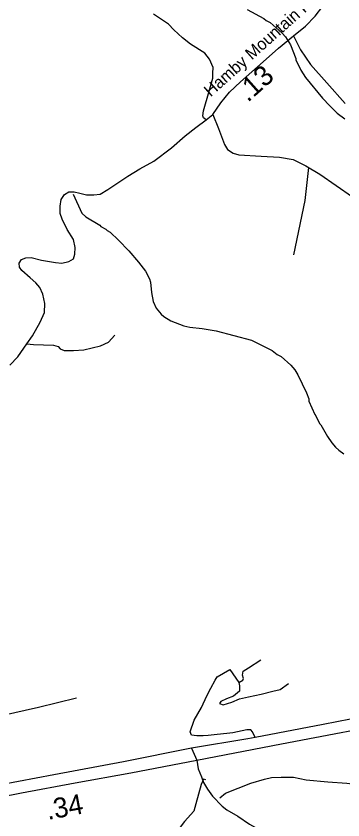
# Model space of a CAD drawing. Extents: x 1248224 to 1454986, y 825081 to 985870.
# Drawn here: x 1325316 to 1327358, y 878794 to 883811 of the extents above; entities that cross this region are included whole.
import ezdxf

# ---------------------------------------------------------------- set-up
doc = ezdxf.new("R2010")
doc.units = 0
for name, color, linetype in [('Exist Hydrographic Misc Water Feature', 7, 'Continuous'), ('Exist Road Non-System Type 51', 7, 'Continuous'), ('Exist Road Primary US Divided Attributed', 7, 'Continuous'), ('Exist Road Primary US Mileage Hundredths English Label', 7, 'Continuous'), ('Exist Road Secondary Mileage Hundredths English Label', 7, 'Continuous'), ('Exist Road Secondary Type 51 Attributed', 7, 'Continuous'), ('Exist Road Secondary Type 51 Label', 7, 'Continuous')]:
    doc.layers.add(name, color=color, linetype=linetype)

msp = doc.modelspace()

# ---------------------------------------------------------------- linework, layer by layer
at = {"layer": 'Exist Hydrographic Misc Water Feature'}
for points in [[(1326760.7, 883851.5), (1326863.2, 883796.6), (1326878.9, 883784.2), (1326902.6, 883771.5), (1326978.7, 883705.2), (1327000, 883680.6), (1327030.7, 883631.8), (1327064.3, 883546.8), (1327064.1, 883538.8), (1327094.2, 883474), (1327125, 883427.1), (1327231.4, 883298.1), (1327276.1, 883250.8), (1327322.9, 883205.5), (1327369.8, 883170.2)], [(1325671.9, 882699.4), (1325726.6, 882581.9), (1325752, 882557.2), (1325838.5, 882506.6), (1325846.3, 882498.4), (1325877.9, 882481.5), (1325885.7, 882473.3), (1325903.3, 882462.7), (1325956, 882413.3), (1326020.1, 882345.4), (1326080.2, 882275.7), (1326124.5, 882218.4), (1326149.3, 882171.8), (1326156.6, 882149.5), (1326162.8, 882085.4), (1326173.2, 882029.1), (1326192.1, 881988.5), (1326223.1, 881949.7), (1326238.7, 881935.2), (1326284, 881909.9), (1326365.1, 881877.6), (1326400.9, 881868.6), (1326478.7, 881860.3), (1326566.2, 881845.8), (1326786.7, 881787.4), (1326917, 881723.7), (1326948.2, 881698.8), (1326971.9, 881686.1), (1327032.4, 881632.4), (1327057.6, 881603.7), (1327076.7, 881571.2), (1327129.6, 881459.6), (1327144.6, 881421.2), (1327146.1, 881407.1), (1327181.9, 881324.2), (1327189.6, 881316), (1327212.2, 881267.3), (1327220, 881259.1), (1327262, 881185.9), (1327288.9, 881147.1), (1327312.2, 881120.5), (1327331.7, 881101.9), (1327363.1, 881079)]]:
    msp.add_lwpolyline(points, dxfattribs=at)
at = {"layer": 'Exist Road Non-System Type 51'}
for points in [[(1326504, 883163.7), (1326488.1, 883176), (1326482.1, 883188), (1326486.1, 883220), (1326522.1, 883342), (1326546.1, 883424), (1326546.1, 883454.1), (1326548, 883490.1), (1326524.1, 883542.1), (1326496.1, 883580.1), (1326406.1, 883636.1), (1326356.2, 883676.1), (1326302.2, 883726.1), (1326268.2, 883760.1), (1326174.3, 883822.1)], [(1327143.1, 882865), (1327119.7, 882659.6), (1327049.3, 882321.2)], [(1325384.1, 881765), (1325425.4, 881760.3), (1325550.5, 881756), (1325578.6, 881749.5), (1325591.5, 881734.4), (1325617.4, 881723.6), (1325675.7, 881723.6), (1325740.4, 881727.9), (1325792.2, 881740.8), (1325844, 881753.8), (1325893.7, 881775.4), (1325932.5, 881818.6)], [(1326707.6, 879651), (1326732.7, 879665.4), (1326736.3, 879676.2), (1326730.9, 879697.7), (1326734.5, 879721.1), (1326768.7, 879742.7), (1326845.9, 879793)], [(1326810.7, 879308.3), (1326792.7, 879344.3), (1326781.9, 879356.9), (1326758.6, 879356.9), (1326670.5, 879337.1), (1326632.8, 879333.5), (1326573.5, 879326.3), (1326516, 879320.9), (1326485.5, 879319.1), (1326446, 879319.1), (1326411.8, 879322.7), (1326404.6, 879344.3), (1326428, 879416.2), (1326474.7, 879495.3), (1326507, 879568.6), (1326533.9, 879615.3), (1326560.9, 879665.7), (1326573.5, 879687.2), (1326652.5, 879732.2)], [(1326652.5, 879732.2), (1326707.6, 879651), (1326713, 879631.2), (1326713, 879616.8), (1326711.2, 879597), (1326675.3, 879566.5), (1326630.3, 879550.3), (1326596.2, 879532.3), (1326587.2, 879519.7), (1326610.6, 879512.5), (1326664.5, 879528.7), (1326711.2, 879550.3), (1326768.7, 879561.1), (1326847.7, 879579.1), (1326919.6, 879597), (1326966.3, 879607.8), (1327018.4, 879645.6)], [(1325131.9, 879422.7), (1325225.8, 879446.3), (1325455.8, 879496.6), (1325692.9, 879556)], [(1326502, 879044.7), (1326487.5, 879048.1), (1326473.1, 879014), (1326439, 878893.5), (1326426.4, 878848.6), (1326368.9, 878783.8), (1326322.2, 878722.7), (1326207.2, 878634.6), (1326165.9, 878584.3), (1326108.4, 878510.6), (1326083.3, 878463.8), (1326086.9, 878415.3), (1326112, 878345.1), (1326155.1, 878249.9)], [(1326589.1, 878930.6), (1326625.2, 878961), (1326783.3, 879022.1), (1326867.8, 879047.3), (1326912.7, 879058.1), (1326972, 879059.9), (1327049.2, 879059.9), (1327128.3, 879043.7), (1327263, 879031.1), (1327383.4, 879022.1), (1327493, 879007.7), (1327591.8, 879002.3), (1327633.1, 878996.9), (1327701.4, 878980.7), (1327732, 878937.6)]]:
    msp.add_lwpolyline(points, dxfattribs=at)
at = {"layer": 'Exist Road Primary US Divided Attributed'}
for points in [[(1328926.5, 879708.9), (1328668.2, 879655.3), (1328025.6, 879542), (1327490.9, 879439), (1327233.7, 879388.2), (1326810.7, 879308.3), (1326763.7, 879300.6), (1326412.6, 879240.6)], [(1326445.7, 879166.7), (1326974.8, 879268.1), (1327762.8, 879419), (1328042, 879466.3), (1328746.8, 879606), (1328958.4, 879644.3)], [(1326412.6, 879240.6), (1325988, 879155.2), (1325552.1, 879075.7), (1325219.9, 879012.4), (1324673.4, 878905.9)], [(1324691.7, 878831.1), (1324946.2, 878882.9), (1325349.2, 878961.8), (1325684.7, 879024.8), (1326033.6, 879087.9), (1326445.7, 879166.7)]]:
    msp.add_lwpolyline(points, dxfattribs=at)
at = {"layer": 'Exist Road Secondary Type 51 Attributed'}
for points in [[(1327050.3, 883687.5), (1327123.6, 883748.4), (1327184.1, 883810.6), (1327233.5, 883872.8)], [(1326546.3, 883196.1), (1326595.7, 883270.6), (1326649.5, 883336.7), (1326718.6, 883399.7), (1326859.9, 883525.7), (1326956.6, 883610.3), (1327050.3, 883687.5)], [(1327050.3, 883687.5), (1327093.7, 883600.7), (1327155.8, 883508.1), (1327258.5, 883395.3), (1327371.2, 883265.2)], [(1325278.1, 881632.8), (1325327.2, 881685), (1325384.1, 881765), (1325419.1, 881814.7), (1325466.7, 881900.8), (1325492.8, 881960.8), (1325495.9, 882016.1), (1325483.6, 882076), (1325463.6, 882116), (1325439.1, 882145.2), (1325403.7, 882177.5), (1325351.5, 882222.1), (1325337.7, 882243.6), (1325334.6, 882269.7), (1325350, 882291.2), (1325377.6, 882302), (1325409.9, 882303.5), (1325474.4, 882288.1), (1325561.9, 882272.8), (1325601.9, 882269.7), (1325644.9, 882278.9), (1325674, 882295.8), (1325683.3, 882325), (1325686, 882366.8), (1325675.2, 882416), (1325635.3, 882479), (1325603.1, 882543.6), (1325590.8, 882578.9), (1325590.8, 882625), (1325596.9, 882666.5), (1325618.4, 882697.3), (1325646.1, 882714.2), (1325678.3, 882714.2), (1325713.6, 882705), (1325756.6, 882695.7), (1325802.7, 882695.7), (1325841.1, 882700.3), (1325890.3, 882728), (1326014.7, 882811), (1326089.9, 882857.1), (1326177.4, 882906.3), (1326287.5, 882988.5), (1326371.9, 883063.8), (1326439.5, 883116), (1326504, 883163.7), (1326546.3, 883196.1)], [(1326546.3, 883196.1), (1326579.9, 883109.1), (1326618, 883009.9), (1326637.9, 882979.3), (1326671.4, 882954.9), (1326708, 882944.2), (1326846.8, 882936.6), (1326962.7, 882930.5), (1327048.1, 882915.2), (1327125.9, 882877.1), (1327214.4, 882823.6), (1327418.8, 882683.2)], [(1326412.6, 879240.6), (1326445.7, 879166.7)], [(1326445.7, 879166.7), (1326454.5, 879112.5), (1326474.3, 879061.9), (1326486.9, 879027.3), (1326511.1, 878986.6), (1326543, 878941.5), (1326602.9, 878879.8), (1326633.1, 878856.8), (1326700.9, 878816.5), (1326774.7, 878767.2), (1326886.4, 878704.6), (1327038.5, 878619.6), (1327203.3, 878533.3), (1327239.1, 878499.7), (1327250.2, 878468.4), (1327256.9, 878396.8), (1327261.4, 878260.4), (1327270.3, 878184.3), (1327306.1, 878045.6), (1327339.6, 877919.1), (1327369.5, 877837.4), (1327397.7, 877762.4), (1327435.7, 877690.9), (1327496, 877601.4)]]:
    msp.add_lwpolyline(points, dxfattribs=at)

# ---------------------------------------------------------------- texts
at = {"layer": 'Exist Road Primary US Mileage Hundredths English Label'}
msp.add_text('.34', height=125, rotation=10.3316, dxfattribs=at).set_placement((1325515, 878793.3))
at = {"layer": 'Exist Road Secondary Mileage Hundredths English Label'}
msp.add_text('.13', height=125, rotation=41.7334, dxfattribs=at).set_placement((1326763.6, 883268.8))
at = {"layer": 'Exist Road Secondary Type 51 Label'}
msp.add_text('Hamby Mountain Rd', height=75, rotation=41.7583, dxfattribs=at).set_placement((1326531, 883303.5))

doc.saveas('drawing.dxf')
